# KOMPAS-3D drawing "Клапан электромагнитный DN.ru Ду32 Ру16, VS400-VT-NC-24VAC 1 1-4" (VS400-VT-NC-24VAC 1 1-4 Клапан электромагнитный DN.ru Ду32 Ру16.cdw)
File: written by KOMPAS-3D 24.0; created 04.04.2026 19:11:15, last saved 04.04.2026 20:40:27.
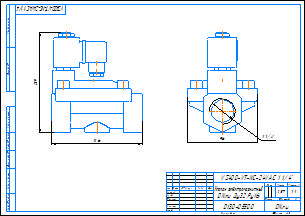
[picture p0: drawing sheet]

Document properties: c3d_UniqueCompID: ef56311e-7521-43dc-8291-0e6108b3d81d; Обозначение: VS400-ET-NC-220VAC 1; Наименование: Клапан электромагнитный DN.ru Ду25 Ру16; Автор: artio; Класс точности: c; Знак неуказанной шероховатости: Шероховатость не задана; Рассекать на разрезах: Да; c3d_UniqueCompID: ef56311e-7521-43dc-8291-0e6108b3d81d; Обозначение: VS400-ET-NC-220VAC 1-2; Наименование: Клапан электромагнитный DN.ru Ду15 Ру16; Автор: artio; Класс точности: c; Знак неуказанной шероховатости: Шероховатость не задана; Рассекать на разрезах: Да; c3d_UniqueCompID: ef56311e-7521-43dc-8291-0e6108b3d81d; Обозначение: VS400-ET-NC-220VAC 3-4; Наименование: Клапан электромагнитный DN.ru Ду20 Ру16; Автор: artio; Класс точности: c; Знак неуказанной шероховатости: Шероховатость не задана; Рассекать на разрезах: Да; c3d_UniqueCompID: ef56311e-7521-43dc-8291-0e6108b3d81d; Обозначение: VS400-ET-NC-220VAC 1 1-4; Наименование: Клапан электромагнитный DN.ru Ду32 Ру16; Автор: artio; Класс точности: c; Знак неуказанной шероховатости: Шероховатость не задана; Рассекать на разрезах: Да; c3d_UniqueCompID: ef56311e-7521-43dc-8291-0e6108b3d81d; Обозначение: VS400-ET-NC-220VAC 3-8; Наименование: Клапан электромагнитный DN.ru Ду10 Ру16; Автор: artio; Класс точности: c; Знак неуказанной шероховатости: Шероховатость не задана; Рассекать на разрезах: Да; Автор: artio; Форматы листов документа: A3; Полное имя файла: VS400-VT-NC-24VAC 1 1-4 Клапан электромагнитный DN.ru Ду32 Ру16.m3d; Масса: 2.569; Наименование: Клапан электромагнитный DN.ru Ду32 Ру16; Количество листов документа: 1; Примечание: D130-05500

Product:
- Body: Тело 1  | qty 1
    Масса: 4.144257
- Part/product: Клапан электромагнитный DN.ru Ду32 Ру16  | designation VS400-VT-NC-24VAC 1 1-4
    Масса: 2.569
    Раздел спецификации: Прочие изделия
    Примечание: D130-05500
    additional columns: ef56311e-7521-43dc-8291-0e6108b3d81d; VS400-ET-NC-220VAC 1 1-4; artio; c; Шероховатость не задана; Да

Views: Вид 1, Спереди
Referenced files in C:\Users\artio\OneDrive\Рабочий стол\Клапан электромагнитный DN.ru\VS400-ET-NC\VS400-ET-NC-24VDC\: VS400-ET-NC-24VDC 3-8 Клапан электромагнитный DN.ru Ду10 Ру16.m3d
Referenced files in C:\Users\artio\OneDrive\Рабочий стол\Клапан электромагнитный DN.ru\VS400-VT-NC\VS400-VT-NC-24VAC\: VS400-VT-NC-24VAC 1 1-4 Клапан электромагнитный DN.ru Ду32 Ру16.m3d
Referenced files in C:\Users\artio\OneDrive\Рабочий стол\Клапан электромагнитный DN.ru\VS400-ET-NC\: VS400-ET-NC-24VDC 3-8 Клапан электромагнитный DN.ru Ду10 Ру16.cdw
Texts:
  VS400-VT-NC-24VAC 1 1-4
  Клапан электромагнитный
  DN.ru Ду32 Ру16
  VS400-VT-NC-24VAC 1 1/4"
  VS400-VT-NC-24VAC 1 1/4"-
  Клапан электромагнитный DN.ru Ду32 Ру16
  VS400-VT-NC-24VAC 1 1-4 Клапан электромагнитный DN.ru Ду32 Ру16
Dimensions and other numbers on the sheet: 0; 3; 2; 4; 96; 1 1/4"; 1:1; 1; 2,57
